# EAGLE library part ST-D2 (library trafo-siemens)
TRANSFORMER
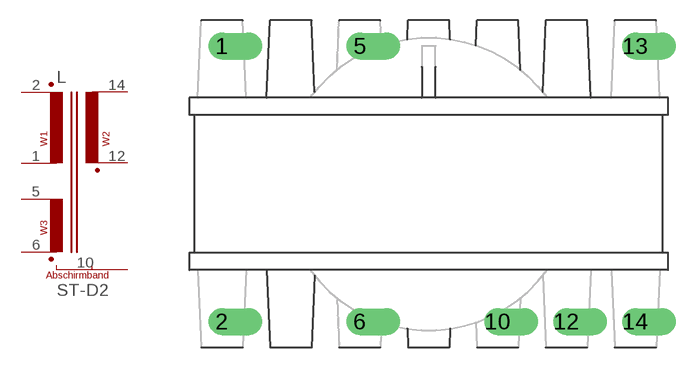
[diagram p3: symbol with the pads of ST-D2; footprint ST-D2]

Designator prefix L

## ST-D2  [ST-D2]
1  1E  pas
2  1A  pas
5  3E  pas
6  3A  pas
10  SCH  pas
12  2A  pas
13  SCH1  pas
14  2E  pas

## Footprint ST-D2 (pad centres in mm)
TRANSFORMER
drill 1.321 offset: 1 -15.24,10.16; 2 -15.24,-10.16; 5 -5.08,10.16; 6 -5.08,-10.16; 10 5.08,-10.16; 12 10.16,-10.16; 13 15.24,10.16; 14 15.24,-10.16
